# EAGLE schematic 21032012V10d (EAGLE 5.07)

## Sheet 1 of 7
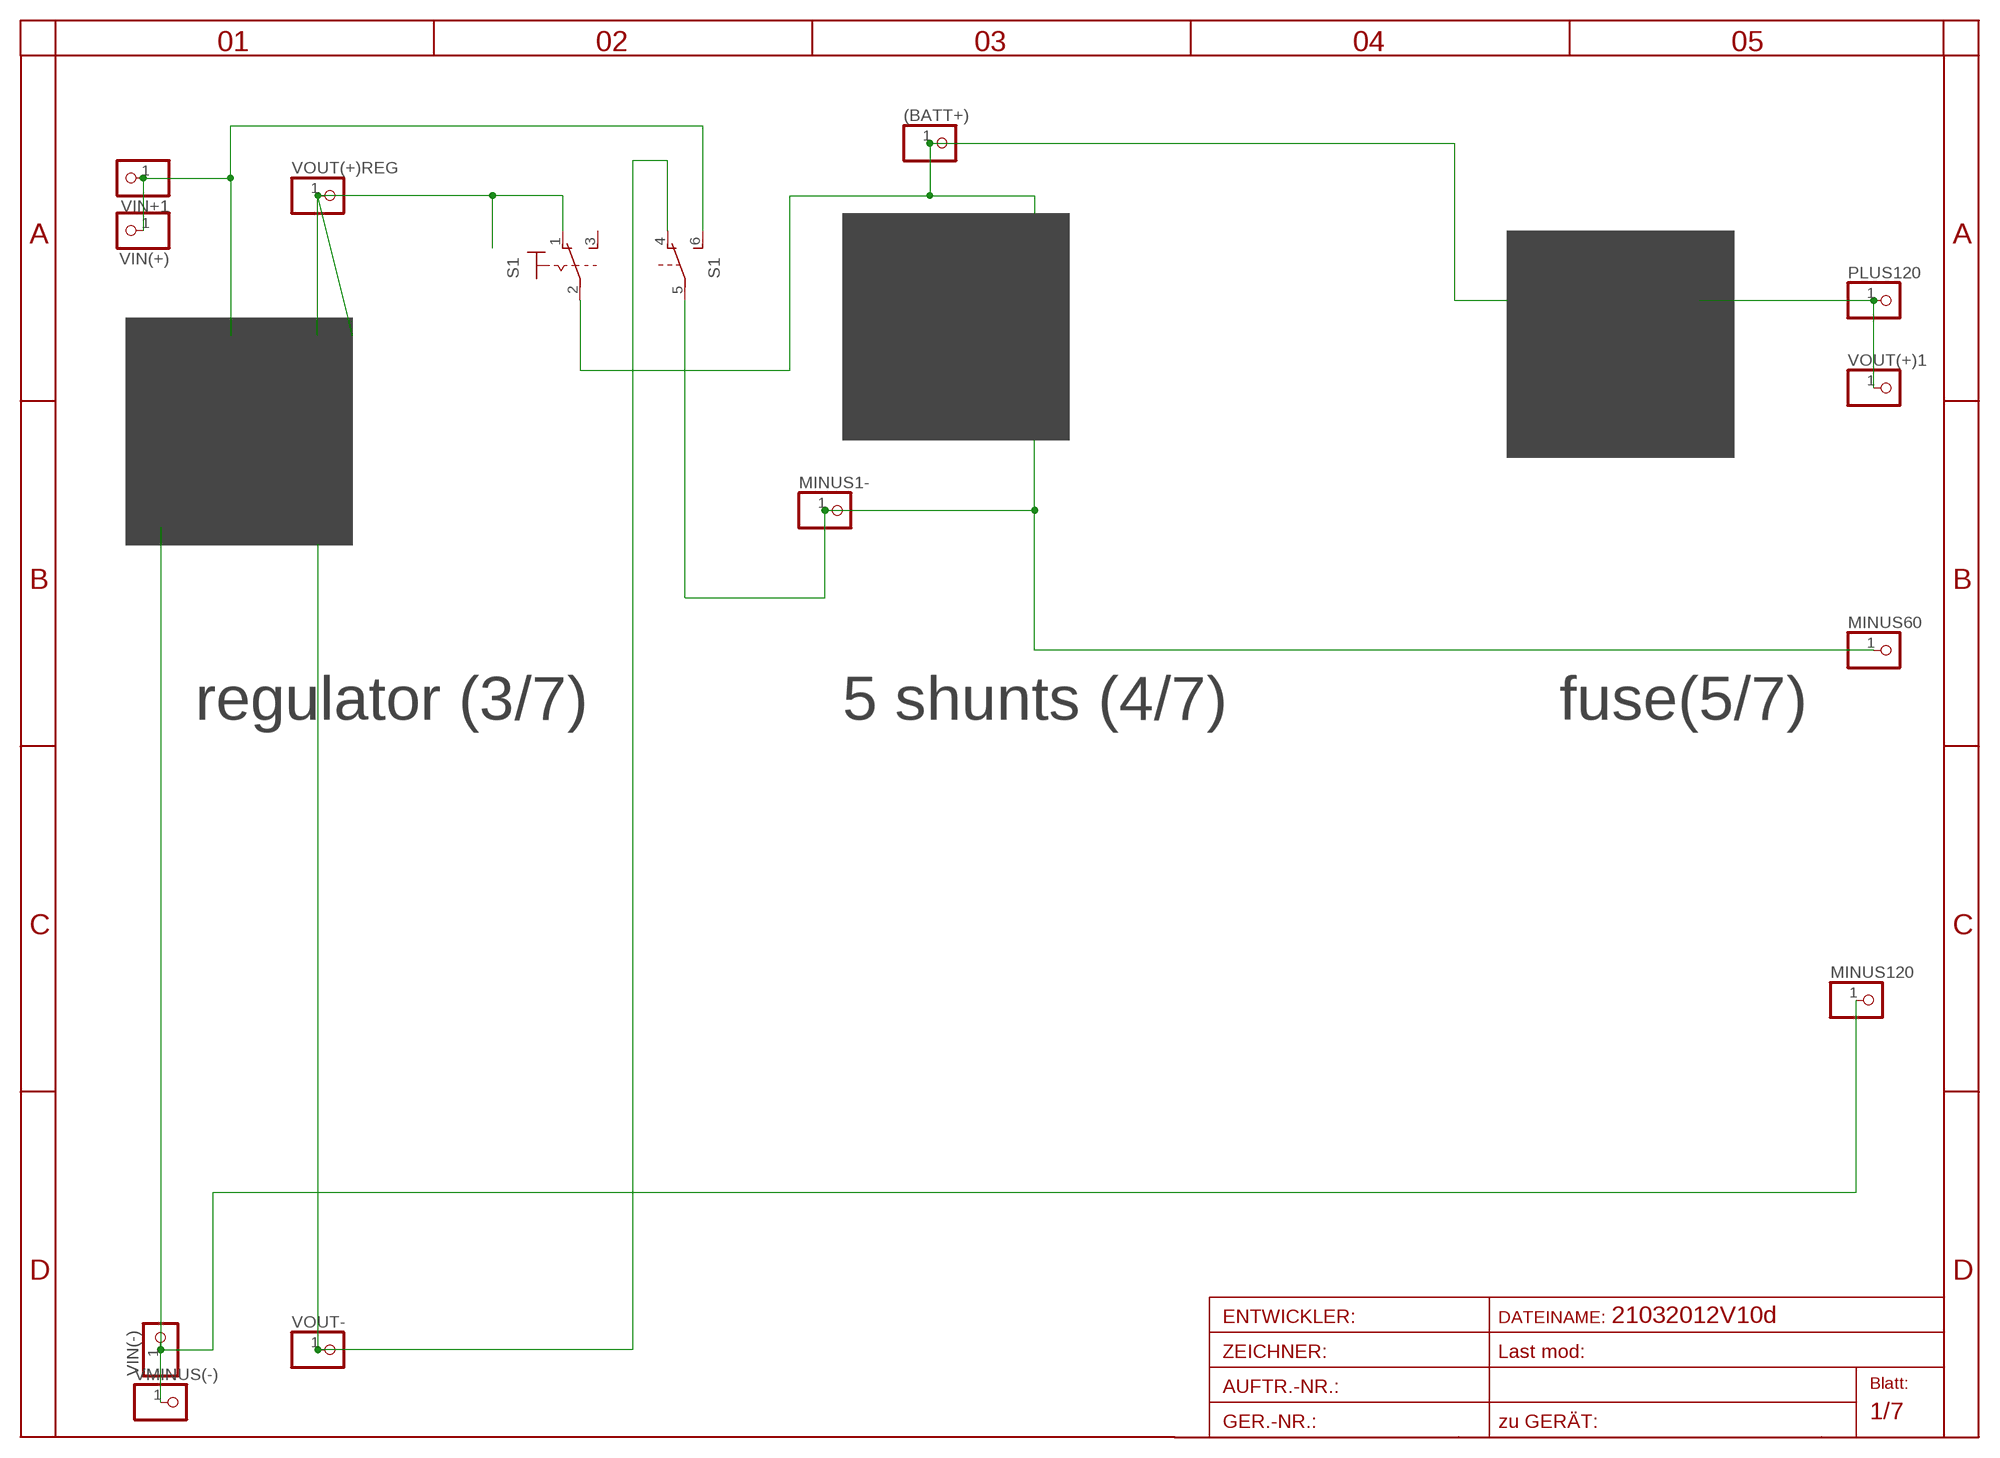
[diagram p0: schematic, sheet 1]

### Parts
(BATT+)  PINHD-1X14.5MM  [1X4MM5]
MINUS1-  PINHD-1X14.5MM  [1X4MM5]
MINUS60  PINHD-1X14.5MM  [1X4MM5]
MINUS120  PINHD-1X14.5MM  [1X4MM5]
PLUS120  PINHD-1X14.5MM  [1X4MM5]
S1  320-938320NEW  [320NEW]
VIN(+)  PINHD-1X11MM6  [1X1MM8]
VIN(-)  PINHD-1X1  [1X01]
VIN+1  PINHD-1X1  [1X01]
VMINUS(-)  PINHD-1X11MM6  [1X1MM8]
VOUT(+)1  PINHD-1X11X0.4  [1X01]
VOUT(+)REG  PINHD-1X11X0.4  [1X01]
VOUT-  PINHD-1X11X0.4  [1X01]

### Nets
BATT-: MINUS1-.1 MINUS60.1 S1.5(B:P) ; also sheet 4,5,6,7
IN-: MINUS120.1 VIN(-).1 VMINUS(-).1 ; also sheet 3
PLUS11: (BATT+).1 S1.2(1:P) ; also sheet 4,5,6,7
V+OUT: PLUS120.1 VOUT(+)1.1 ; also sheet 5
V-: S1.4(B:O) VOUT-.1 ; also sheet 3
VIN+: S1.6(B:S) VIN(+).1 VIN+1.1 ; also sheet 3
VOUT+REG: S1.1(1:O) VOUT(+)REG.1 ; also sheet 3
Unconnected: S1.3(1:S)

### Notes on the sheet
- regulator (3/7) | 5 shunts (4/7) | fuse(5/7)

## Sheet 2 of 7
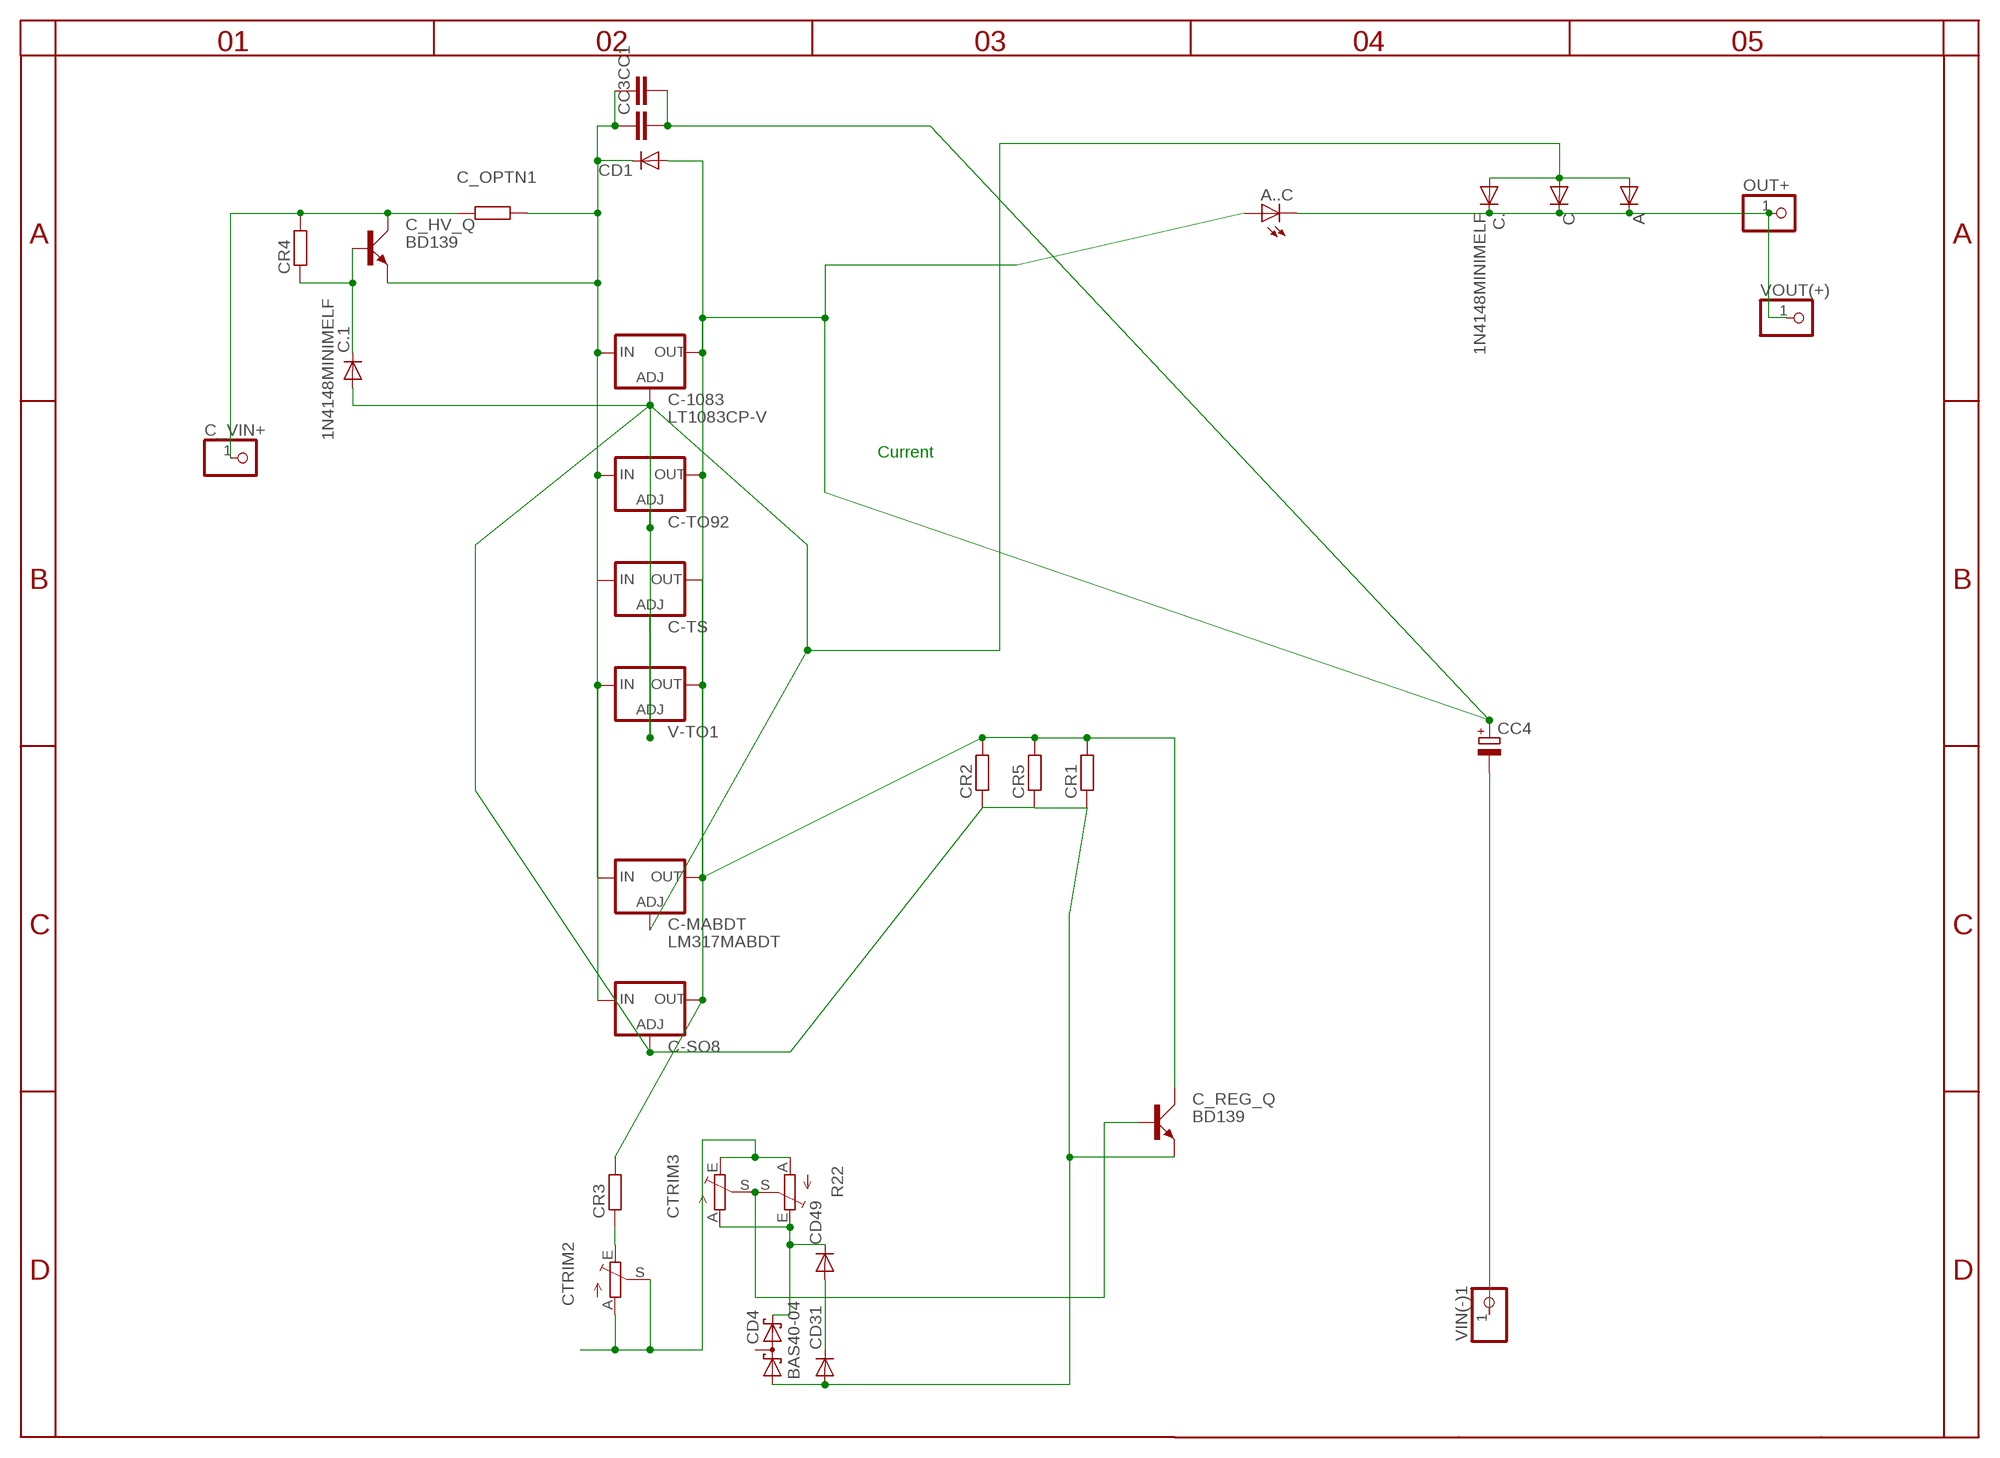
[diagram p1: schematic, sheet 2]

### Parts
A  DIODE-TO220V  [TO220ACS]
A..C  LED3MM  [LED3MM]
C  DIODE-SMB  [SMB]
C-1083  LT1083CP-V  [TO247S]
C-MABDT  LM317MABDT  [DPACK]
C-SO8  LM317LM-OUTPIN7  [SO08]
C-TO92  LM317LZS  [TO92S]
C-TS  LM317TS  [317TS]
C.  1N4148MINIMELF  [MINIMELF]
C.1  1N4148MINIMELF  [MINIMELF]
C_HV_Q  BD139  [TO126AV]
C_OPTN1  R-EU_R0805  [R0805]
C_REG_Q  BD139  [TO126AV]
C_VIN+  PINHD-1X11MM6  [1X1MM8]
CC1  C-EUC1206  [C1206]
CC3  C-EU050-025X075  [C050-025X075]
CC4  CPOL-EUE5-6  [E5-6]
CD1  DIODE-MINIMELF  [MINIMELF]
CD4  BAS40-04  [SOT23]
CD31  DIODE-MINIMELF  [MINIMELF]
CD49  DIODE-MINIMELF  [MINIMELF]
CR1  R-EU_R5025  [R5025]
CR2  R-EU_R1206  [R1206]
CR3  R-EU_R1206  [R1206]
CR4  R-EU_R1206  [R1206]
CR5  R-EU_R1210  [R1210]
CTRIM2  TRIM_EU-EVND_H  [EVND8AA]
CTRIM3  TRIM_EU-EVND_H  [EVND8AA]
OUT+  PINHD-1X1  [1X01]
R22  TRIM_EU-RAND160  [RANDL]
V-TO1  LM317-TO3  [TO3-K02]
VIN(-)1  PINHD-1X1  [1X01]
VOUT(+)  PINHD-1X11X0.4  [1X01]

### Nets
ADJUST: A.A C-1083.1(ADJ) C-MABDT.1(ADJ) C-SO8.4(ADJ) C-TO92.1(ADJ) C-TS.1(ADJ) C.1.A C..A C.A C_REG_Q.E CD4.1(A1) CD31.A CR1.1 CR2.1 CR5.1 V-TO1.2(ADJ)
B1: C_REG_Q.B CTRIM3.S R22.S
INPUT+: C-1083.3(IN) C-MABDT.3(IN) C-SO8.1(IN) C-TO92.3(IN) C-TS.3(IN) C_HV_Q.E C_OPTN1.1 CC1.1 CC3.1 CD1.C V-TO1.1(IN)
MINUS: CD4.2(C2) CD49.C CTRIM3.A R22.E
N$5: CTRIM2.A CTRIM2.S CTRIM3.E R22.A
N$6: CR3.1 CTRIM2.E
N$9: CC4.- VIN(-)1.1
N$54: CD31.C CD49.A
N$84: C.1.C C_HV_Q.B CR4.1
N$85: C_HV_Q.C C_OPTN1.2 C_VIN+.1 CR4.2
OUT1: A..C.A C-1083.2(OUT) C-MABDT.4(OUT) C-SO8.7(OUT) C-TO92.2(OUT) C-TS.2(OUT) C_REG_Q.C CC1.2 CC3.2 CC4.+ CD1.A CR1.2 CR2.2 CR3.2 CR5.2 V-TO1.3(OUT)
OUT+: A..C.K(C) A.C C..C C.C OUT+.1 VOUT(+).1
Unconnected: CD4.3(C1A2)

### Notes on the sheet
- Current

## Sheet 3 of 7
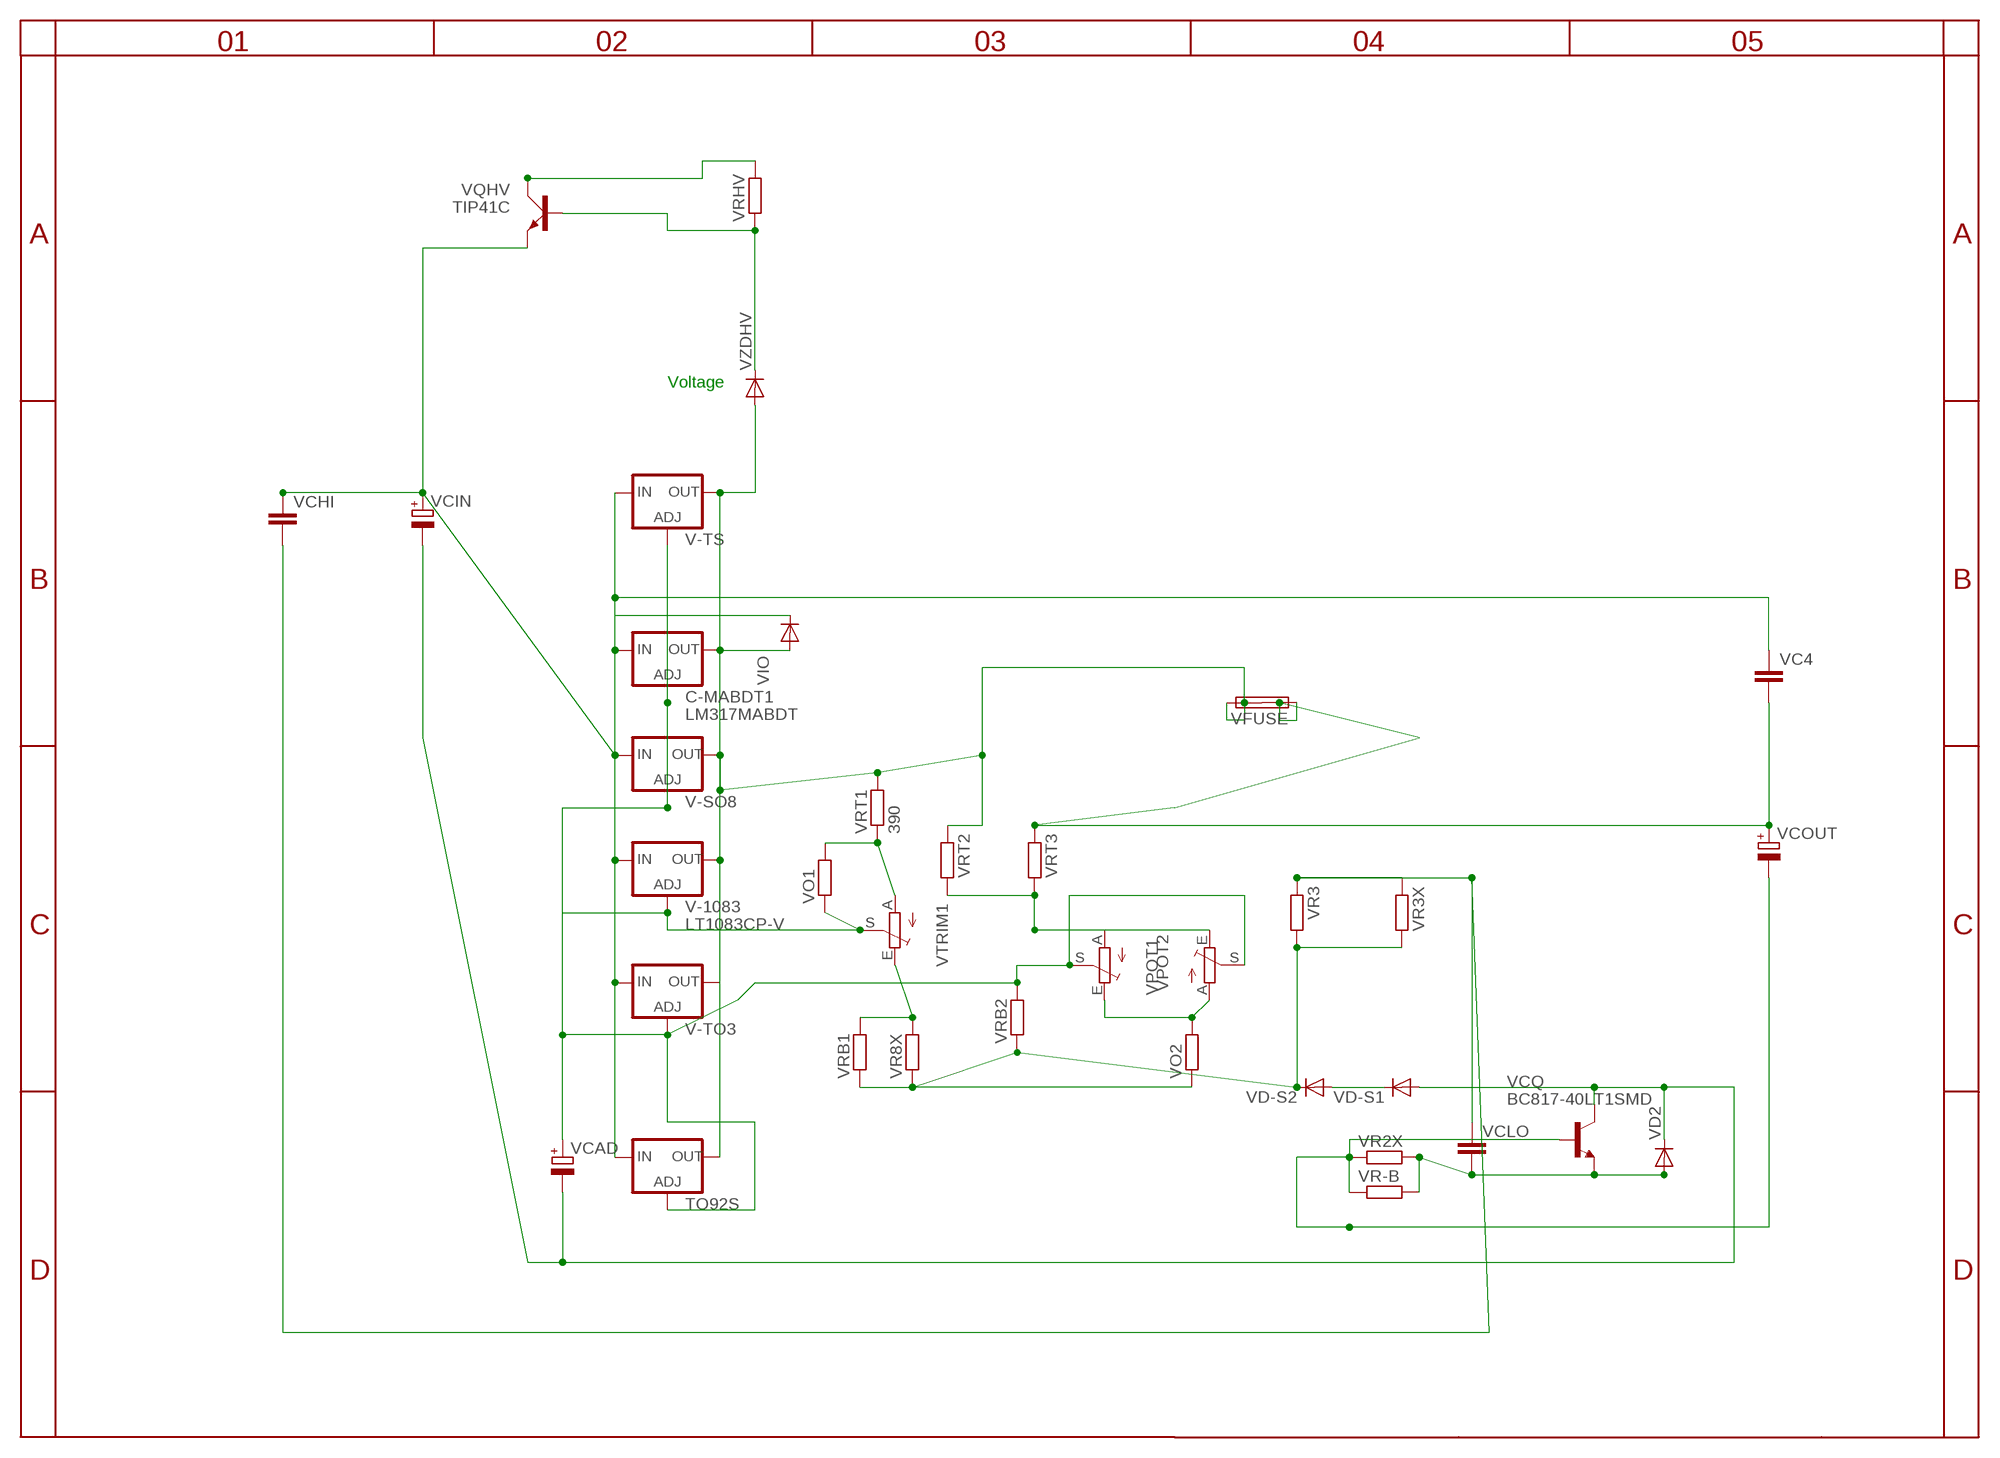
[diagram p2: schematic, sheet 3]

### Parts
C-MABDT1  LM317MABDT  [DPACK]
TO92S  LM317LZS  [TO92S]
V-1083  LT1083CP-V  [TO247S]
V-SO8  LM317LM-OUTPIN7  [SO08]
V-TO3  LM317-TO3  [TO3-K02]
V-TS  LM317TS  [317TS]
VC4  C-EUC1206  [C1206]
VCAD  CPOL-EUE2.5-6  [E2,5-6]
VCHI  C-EU050-025X075  [C050-025X075]
VCIN  CPOL-EUE2.5-6  [E2,5-6]
VCLO  C-EU050-025X075  [C050-025X075]
VCOUT  CPOL-EUE5-8.5  [E5-8,5]
VCQ  BC817-40LT1SMD  [SOT23-BEC]
VD2  DIODE-MINIMELF  [MINIMELF]
VD-S1  DIODE-MINIMELF  [MINIMELF]
VD-S2  DIODE-MINIMELF  [MINIMELF]
VFUSE  SHK20Q  [SHK20Q]
VIO  DIODE-MINIMELF  [MINIMELF]
VO1  R-EU_0204/2V  [0204V]
VO2  R-EU_0204/2V  [0204V]
VPOT1  TRIM_EU-RAND160  [RANDL]
VPOT2  TRIM_EU-S64W  [S64W]
VQHV  TIP41C  [TO220AV]
VR2X  R-EU_0617/17  [0617/17]
VR3  R-EU_0204/5  [0204/5]
VR3X  R-EU_R1206  [R1206]
VR8X  R-EU_0204/2V  [0204V]
VR-B  R-EU_R2010  [R2010]
VRB1  R-EU_R1206  [R1206]
VRB2  R-EU_R1206  [R1206]
VRHV  R-EU_R1206  [R1206]
VRT1  390  R-EU_0207/15  [0207/15]
VRT2  R-EU_R1206  [R1206]
VRT3  R-EU_R1206  [R1206]
VTRIM1  TRIM_EU-EVND_H  [EVND8AA]
VZDHV  DIODE-MINIMELF  [MINIMELF]

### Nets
ADJ2: C-MABDT1.1(ADJ) TO92S.1(ADJ) V-1083.1(ADJ) V-SO8.4(ADJ) V-TO3.2(ADJ) V-TS.1(ADJ) VCAD.+ VO1.1 VPOT1.S VPOT2.S VRB2.2 VTRIM1.S
IN+1: C-MABDT1.3(IN) TO92S.3(IN) V-1083.3(IN) V-SO8.1(IN) V-TO3.1(IN) V-TS.3(IN) VC4.1 VCHI.1 VCIN.+ VIO.C VQHV.E
IN-: VCLO.2 VCQ.E VD2.A VR2X.2 VR-B.2 ; also sheet 1
N$1: VO2.2 VPOT1.E VPOT2.A
N$2: VPOT1.A VPOT2.E VRT2.2 VRT3.2
N$3: VR8X.2 VRB1.2 VTRIM1.E
N$4: VO1.2 VRT1.1 VTRIM1.A
N$7: VCHI.2 VCLO.1 VR3.1 VR3X.1
N$10: VQHV.B VRHV.1 VZDHV.C
N$12: VD-S2.C VO2.1 VR3.2 VR3X.2 VR8X.1 VRB1.1 VRB2.1
N$13: VD-S1.C VD-S2.A
OUT2: C-MABDT1.4(OUT) TO92S.2(OUT) V-1083.2(OUT) V-SO8.7(OUT) V-TO3.3(OUT) V-TS.2(OUT) VFUSE.2A VFUSE.2B VIO.A VRT1.2 VRT2.1 VZDHV.A
V-: VCOUT.- VCQ.B VR2X.1 VR-B.1 ; also sheet 1
VIN+: VQHV.C VRHV.2 ; also sheet 1
VIRT-: VCAD.- VCIN.- VCQ.C VD2.C VD-S1.A
VOUT+REG: VC4.2 VCOUT.+ VFUSE.1A VFUSE.1B VRT3.1 ; also sheet 1

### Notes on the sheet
- Voltage

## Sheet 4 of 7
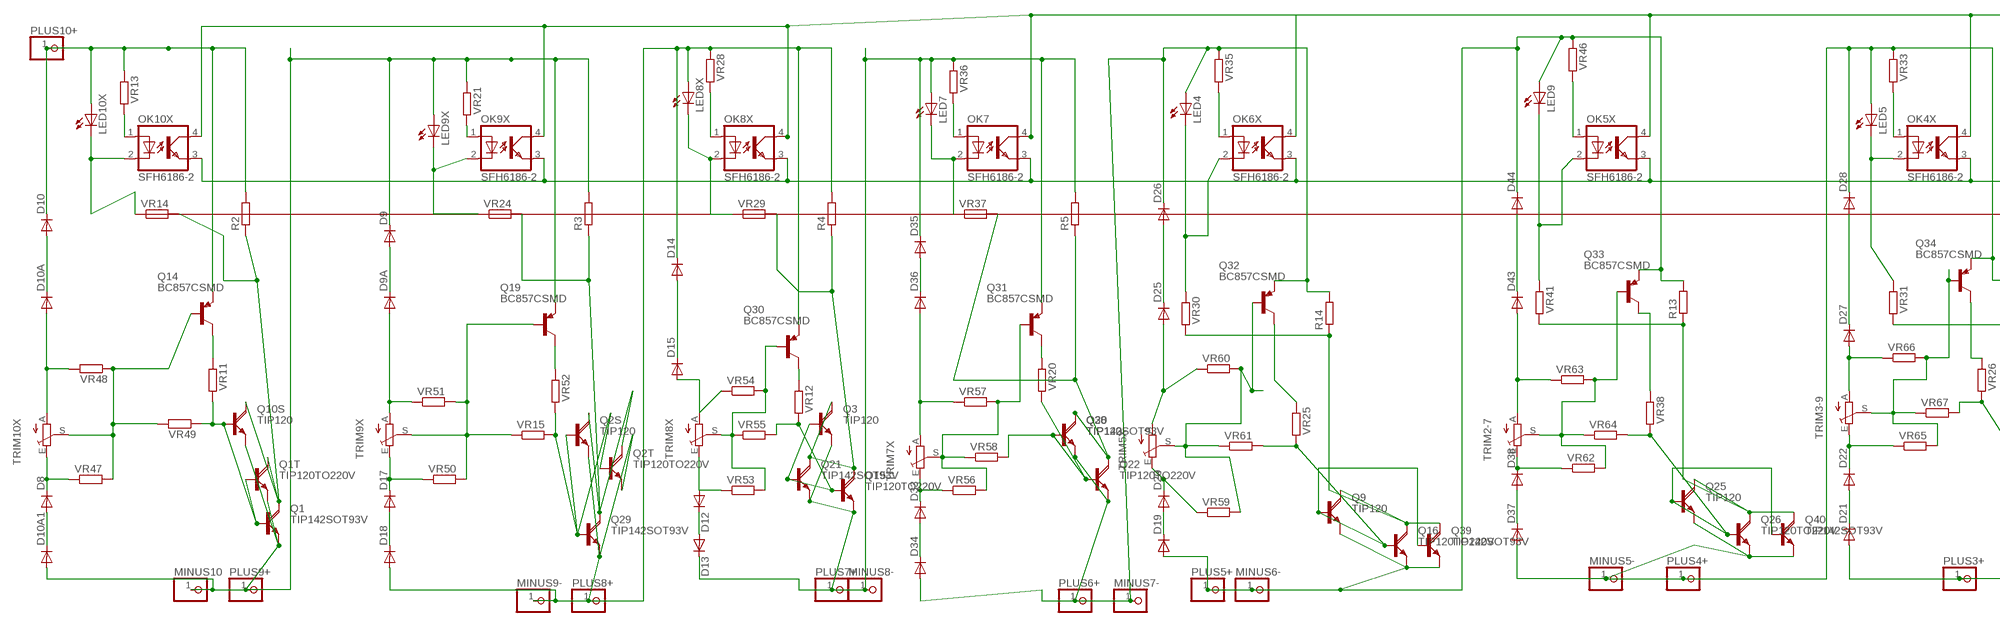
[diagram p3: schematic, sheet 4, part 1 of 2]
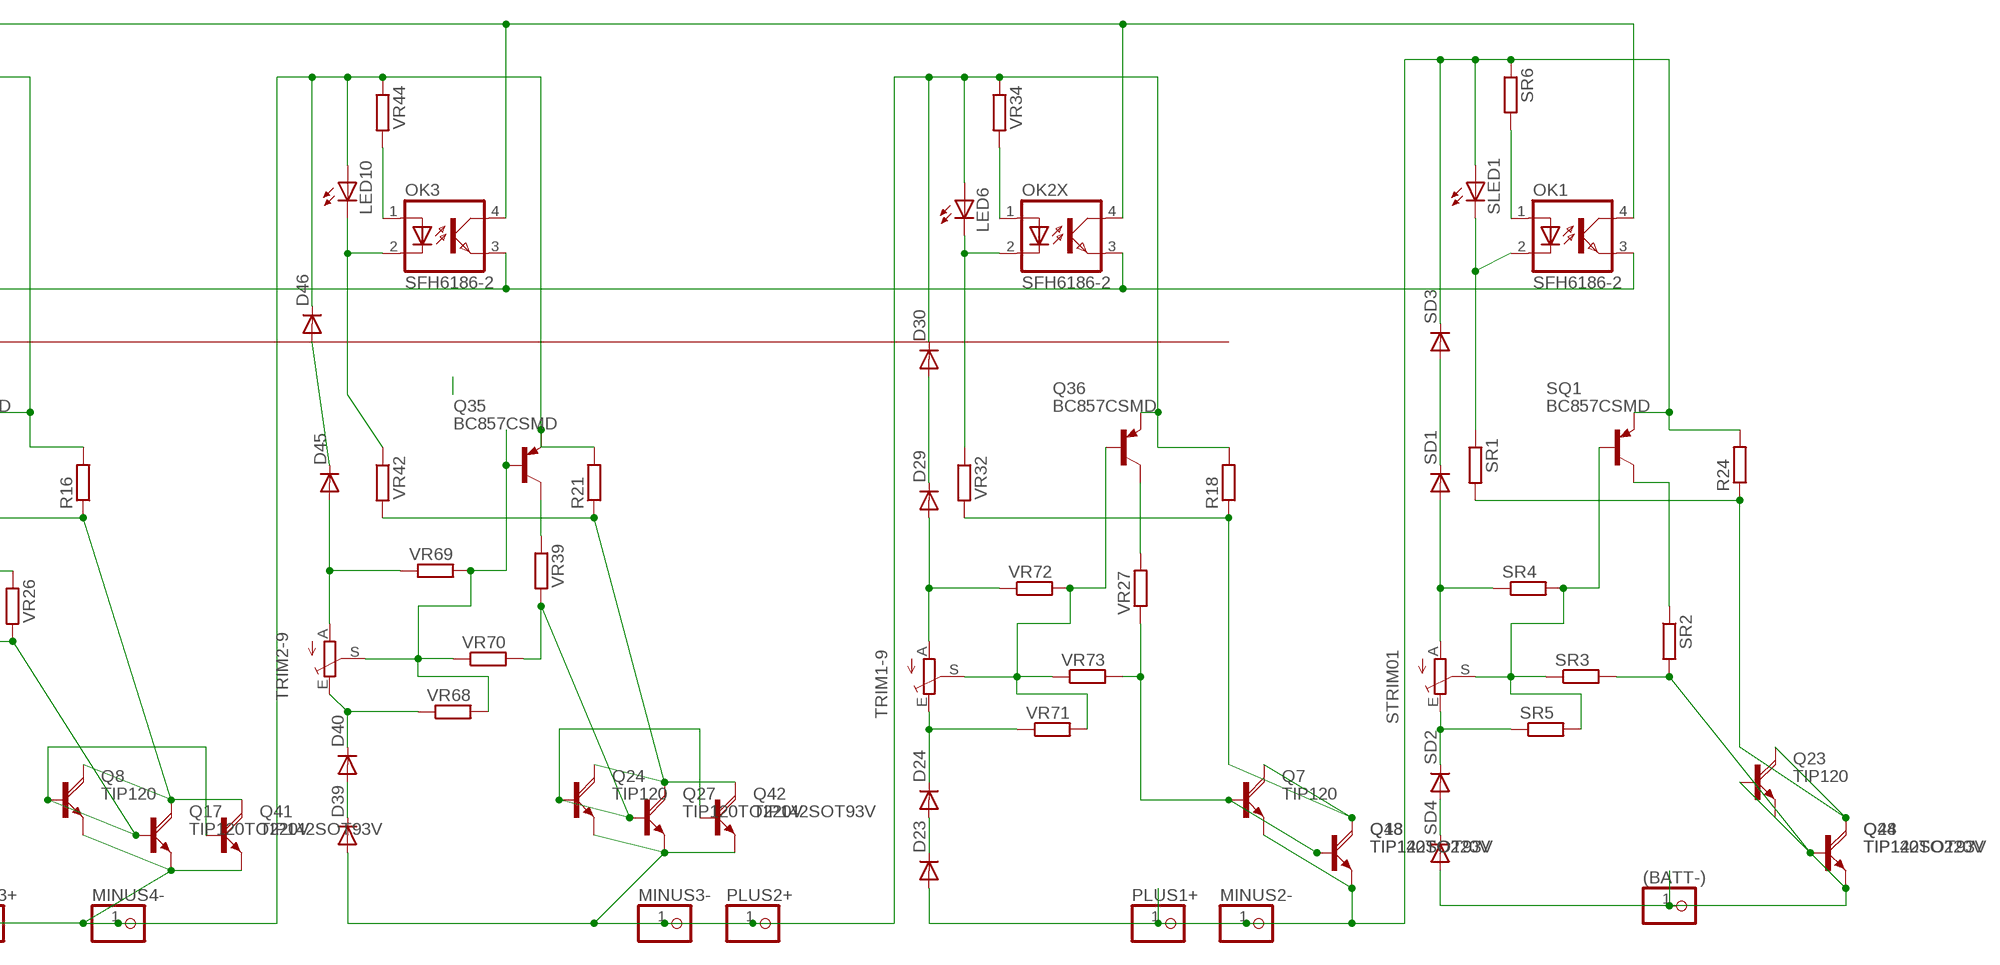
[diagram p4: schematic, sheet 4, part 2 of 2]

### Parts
(BATT-)  PINHD-1X11X0.4  [1X01]
D8  DIODE-MINIMELF  [MINIMELF]
D9  DIODE-MINIMELF  [MINIMELF]
D9A  DIODE-MINIMELF  [MINIMELF]
D10  DIODE-MINIMELF  [MINIMELF]
D10A  DIODE-MINIMELF  [MINIMELF]
D10A1  DIODE-MINIMELF  [MINIMELF]
D12  DIODE-MINIMELF  [MINIMELF]
D13  DIODE-MINIMELF  [MINIMELF]
D14  DIODE-MINIMELF  [MINIMELF]
D15  DIODE-MINIMELF  [MINIMELF]
D17  DIODE-MINIMELF  [MINIMELF]
D18  DIODE-MINIMELF  [MINIMELF]
D19  DIODE-MINIMELF  [MINIMELF]
D20  DIODE-MINIMELF  [MINIMELF]
D21  DIODE-MINIMELF  [MINIMELF]
D22  DIODE-MINIMELF  [MINIMELF]
D23  DIODE-MINIMELF  [MINIMELF]
D24  DIODE-MINIMELF  [MINIMELF]
D25  DIODE-MINIMELF  [MINIMELF]
D26  DIODE-MINIMELF  [MINIMELF]
D27  DIODE-MINIMELF  [MINIMELF]
D28  DIODE-MINIMELF  [MINIMELF]
D29  DIODE-MINIMELF  [MINIMELF]
D30  DIODE-MINIMELF  [MINIMELF]
D33  DIODE-MINIMELF  [MINIMELF]
D34  DIODE-MINIMELF  [MINIMELF]
D35  DIODE-MINIMELF  [MINIMELF]
D36  DIODE-MINIMELF  [MINIMELF]
D37  DIODE-MINIMELF  [MINIMELF]
D38  DIODE-MINIMELF  [MINIMELF]
D39  DIODE-MINIMELF  [MINIMELF]
D40  DIODE-MINIMELF  [MINIMELF]
D43  DIODE-MINIMELF  [MINIMELF]
D44  DIODE-MINIMELF  [MINIMELF]
D45  DIODE-MINIMELF  [MINIMELF]
D46  DIODE-MINIMELF  [MINIMELF]
LED4  LEDCHIPLED_1206  [CHIPLED_1206]
LED5  LEDCHIPLED_1206  [CHIPLED_1206]
LED6  LEDCHIPLED_1206  [CHIPLED_1206]
LED7  LEDCHIPLED_1206  [CHIPLED_1206]
LED8X  LEDCHIPLED_1206  [CHIPLED_1206]
LED9  LEDCHIPLED_1206  [CHIPLED_1206]
LED9X  LEDCHIPLED_1206  [CHIPLED_1206]
LED10  LEDCHIPLED_1206  [CHIPLED_1206]
LED10X  LEDCHIPLED_1206  [CHIPLED_1206]
MINUS2-  PINHD-1X14.5MM  [1X4MM5]
MINUS3-  PINHD-1X14.5MM  [1X4MM5]
MINUS4-  PINHD-1X14.5MM  [1X4MM5]
MINUS5-  PINHD-1X14.5MM  [1X4MM5]
MINUS6-  PINHD-1X14.5MM  [1X4MM5]
MINUS7-  PINHD-1X14.5MM  [1X4MM5]
MINUS8-  PINHD-1X14.5MM  [1X4MM5]
MINUS9-  PINHD-1X14.5MM  [1X4MM5]
MINUS10  PINHD-1X14.5MM  [1X4MM5]
OK1  SFH6186-2  [SMD4]
OK2X  SFH6186-2  [SMD4]
OK3  SFH6186-2  [SMD4]
OK4X  SFH6186-2  [SMD4]
OK5X  SFH6186-2  [SMD4]
OK6X  SFH6186-2  [SMD4]
OK7  SFH6186-2  [SMD4]
OK8X  SFH6186-2  [SMD4]
OK9X  SFH6186-2  [SMD4]
OK10X  SFH6186-2  [SMD4]
PLUS1+  PINHD-1X11X0.4  [1X01]
PLUS2+  PINHD-1X11X0.4  [1X01]
PLUS3+  PINHD-1X11X0.4  [1X01]
PLUS4+  PINHD-1X11X0.4  [1X01]
PLUS5+  PINHD-1X11X0.4  [1X01]
PLUS6+  PINHD-1X11X0.4  [1X01]
PLUS7+  PINHD-1X11X0.4  [1X01]
PLUS8+  PINHD-1X11X0.4  [1X01]
PLUS9+  PINHD-1X11X0.4  [1X01]
PLUS10+  PINHD-1X11X0.4  [1X01]
Q1  TIP142SOT93V  [SOT93V]
Q1T  TIP120TO220V  [TO220AV]
Q2S  TIP120  TIP120DPAK  [D-PAK_TO252AA]
Q2T  TIP120TO220V  [TO220AV]
Q3  TIP120  TIP120DPAK  [D-PAK_TO252AA]
Q7  TIP120  TIP120DPAK  [D-PAK_TO252AA]
Q8  TIP120  TIP120DPAK  [D-PAK_TO252AA]
Q9  TIP120  TIP120DPAK  [D-PAK_TO252AA]
Q10S  TIP120  TIP120DPAK  [D-PAK_TO252AA]
Q14  BC857CSMD  [SOT23-BEC]
Q15  TIP120TO220V  [TO220AV]
Q16  TIP120TO220V  [TO220AV]
Q17  TIP120TO220V  [TO220AV]
Q18  TIP120TO220V  [TO220AV]
Q19  BC857CSMD  [SOT23-BEC]
Q20  TIP120  TIP120DPAK  [D-PAK_TO252AA]
Q21  TIP142SOT93V  [SOT93V]
Q22  TIP120TO220V  [TO220AV]
Q23  TIP120  TIP120DPAK  [D-PAK_TO252AA]
Q24  TIP120  TIP120DPAK  [D-PAK_TO252AA]
Q25  TIP120  TIP120DPAK  [D-PAK_TO252AA]
Q26  TIP120TO220V  [TO220AV]
Q27  TIP120TO220V  [TO220AV]
Q28  TIP120TO220V  [TO220AV]
Q29  TIP142SOT93V  [SOT93V]
Q30  BC857CSMD  [SOT23-BEC]
Q31  BC857CSMD  [SOT23-BEC]
Q32  BC857CSMD  [SOT23-BEC]
Q33  BC857CSMD  [SOT23-BEC]
Q34  BC857CSMD  [SOT23-BEC]
Q35  BC857CSMD  [SOT23-BEC]
Q36  BC857CSMD  [SOT23-BEC]
Q38  TIP142SOT93V  [SOT93V]
Q39  TIP142SOT93V  [SOT93V]
Q40  TIP142SOT93V  [SOT93V]
Q41  TIP142SOT93V  [SOT93V]
Q42  TIP142SOT93V  [SOT93V]
Q43  TIP142SOT93V  [SOT93V]
Q44  TIP142SOT93V  [SOT93V]
R2  R-EU_CERAM55  [CERAM55]
R3  R-EU_CERAM55  [CERAM55]
R4  R-EU_CERAM55  [CERAM55]
R5  R-EU_CERAM55  [CERAM55]
R13  R-EU_CERAM55  [CERAM55]
R14  R-EU_CERAM55  [CERAM55]
R16  R-EU_CERAM55  [CERAM55]
R18  R-EU_CERAM55  [CERAM55]
R21  R-EU_CERAM55  [CERAM55]
R24  R-EU_CERAM55  [CERAM55]
SD1  DIODE-MINIMELF  [MINIMELF]
SD2  DIODE-MINIMELF  [MINIMELF]
SD3  DIODE-MINIMELF  [MINIMELF]
SD4  DIODE-MINIMELF  [MINIMELF]
SLED1  LEDCHIPLED_1206  [CHIPLED_1206]
SQ1  BC857CSMD  [SOT23-BEC]
SR1  R-EU_R1206  [R1206]
SR2  R-EU_R1206  [R1206]
SR3  R-EU_R0805  [R0805]
SR4  R-EU_R0805  [R0805]
SR5  R-EU_R0805  [R0805]
SR6  R-EU_R1206  [R1206]
STRIM01  TRIM_EU-S64W  [S64W]
TRIM1-9  TRIM_EU-S64W  [S64W]
TRIM2-7  TRIM_EU-S64W  [S64W]
TRIM2-9  TRIM_EU-S64W  [S64W]
TRIM3-9  TRIM_EU-S64W  [S64W]
TRIM5X  TRIM_EU-S64W  [S64W]
TRIM7X  TRIM_EU-S64W  [S64W]
TRIM8X  TRIM_EU-S64W  [S64W]
TRIM9X  TRIM_EU-S64W  [S64W]
TRIM10X  TRIM_EU-S64W  [S64W]
VR11  R-EU_R1206  [R1206]
VR12  R-EU_R1206  [R1206]
VR13  R-EU_R1206  [R1206]
VR14  R-EU_R1206  [R1206]
VR15  R-EU_R0805  [R0805]
VR20  R-EU_R1206  [R1206]
VR21  R-EU_R1206  [R1206]
VR24  R-EU_R1206  [R1206]
VR25  R-EU_R1206  [R1206]
VR26  R-EU_R1206  [R1206]
VR27  R-EU_R1206  [R1206]
VR28  R-EU_R1206  [R1206]
VR29  R-EU_R1206  [R1206]
VR30  R-EU_R1206  [R1206]
VR31  R-EU_R1206  [R1206]
VR32  R-EU_R1206  [R1206]
VR33  R-EU_R1206  [R1206]
VR34  R-EU_R1206  [R1206]
VR35  R-EU_R1206  [R1206]
VR36  R-EU_R1206  [R1206]
VR37  R-EU_R1206  [R1206]
VR38  R-EU_R1206  [R1206]
VR39  R-EU_R1206  [R1206]
VR41  R-EU_R1206  [R1206]
VR42  R-EU_R1206  [R1206]
VR44  R-EU_R1206  [R1206]
VR46  R-EU_R1206  [R1206]
VR47  R-EU_R0805  [R0805]
VR48  R-EU_R0805  [R0805]
VR49  R-EU_R0805  [R0805]
VR50  R-EU_R0805  [R0805]
VR51  R-EU_R0805  [R0805]
VR52  R-EU_R1206  [R1206]
VR53  R-EU_R0805  [R0805]
VR54  R-EU_R0805  [R0805]
VR55  R-EU_R0805  [R0805]
VR56  R-EU_R0805  [R0805]
VR57  R-EU_R0805  [R0805]
VR58  R-EU_R0805  [R0805]
VR59  R-EU_R0805  [R0805]
VR60  R-EU_R0805  [R0805]
VR61  R-EU_R0805  [R0805]
VR62  R-EU_R0805  [R0805]
VR63  R-EU_R0805  [R0805]
VR64  R-EU_R0805  [R0805]
VR65  R-EU_R0805  [R0805]
VR66  R-EU_R0805  [R0805]
VR67  R-EU_R0805  [R0805]
VR68  R-EU_R0805  [R0805]
VR69  R-EU_R0805  [R0805]
VR70  R-EU_R0805  [R0805]
VR71  R-EU_R0805  [R0805]
VR72  R-EU_R0805  [R0805]
VR73  R-EU_R0805  [R0805]

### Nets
B: Q14.B TRIM10X.S VR47.2 VR48.1 VR49.2
BATT-: (BATT-).1 Q23.3(E) Q28.E Q44.E SD4.A ; also sheet 1,5,6,7
E2: D23.A MINUS2-.1 PLUS1+.1 Q7.3(E) Q18.E Q43.E R24.2 SD3.C SLED1.A SQ1.E SR6.1
E3: D30.C D39.A LED6.A MINUS3-.1 PLUS2+.1 Q24.3(E) Q27.E Q36.E Q42.E R18.2 VR34.1
E4: D21.A D46.C LED10.A MINUS4-.1 PLUS3+.1 Q8.3(E) Q17.E Q35.E Q41.E R21.2 VR44.1
E5: D28.C D37.A LED5.A MINUS5-.1 PLUS4+.1 Q25.3(E) Q26.E Q34.E Q40.E R16.2 VR33.1
E6: D19.A D44.C LED9.A MINUS6-.1 PLUS5+.1 Q9.3(E) Q16.E Q33.E Q39.E R13.2 VR46.1
E7: D26.C D34.A LED4.A MINUS7-.1 PLUS6+.1 Q20.3(E) Q22.E Q32.E Q38.E R14.2 VR35.1
E8: D13.C D35.C LED7.A MINUS8-.1 PLUS7+.1 Q3.3(E) Q15.E Q21.E Q31.E R5.2 VR36.1
E9: D14.C D18.A LED8X.A MINUS9-.1 PLUS8+.1 Q2S.3(E) Q2T.E Q29.E Q30.E R4.2 VR28.1
N$11: LED10X.C OK10X.2(C) VR14.1
N$14: D10A.A TRIM10X.A VR48.2
N$15: Q14.C VR11.1
N$16: OK8X.1(A) VR28.2
N$17: D10.A D10A.C
N$20: D9A.A TRIM9X.A VR51.1
N$23: OK10X.1(A) VR13.2
N$24: D8.A D10A1.C
N$25: Q1.B Q1T.B Q10S.1(B) VR11.2 VR49.1
N$26: D15.A TRIM8X.A VR54.1
N$27: D12.A TRIM8X.E VR53.1
N$29: D14.A D15.C
N$31: LED8X.C OK8X.2(C) VR29.1
N$32: D12.C D13.A
N$33: Q3.1(B) Q15.B Q21.B VR12.2 VR55.2
N$45: Q35.C VR39.1
N$50: Q9.1(B) Q16.B Q39.B VR25.2 VR61.2
N$51: Q8.1(B) Q17.B Q41.B VR26.2 VR67.2
N$52: Q7.1(B) Q18.B Q43.B VR27.1 VR73.2
N$55: D33.A D34.C
N$56: D9.A D9A.C
N$57: D33.C TRIM7X.E VR56.1
N$62: D27.A TRIM3-9.A VR66.1
N$63: D22.C TRIM3-9.E VR65.1
N$64: Q34.B TRIM3-9.S VR65.2 VR66.2 VR67.1
N$65: Q31.B TRIM7X.S VR56.2 VR57.2 VR58.1
N$66: D25.A TRIM5X.A VR60.1
N$67: Q31.C VR20.1
N$68: D19.C D20.A
N$70: D21.C D22.A
N$71: D25.C D26.A
N$72: D20.C TRIM5X.E VR59.1
N$73: D27.C D28.A
N$74: D29.C D30.A
N$77: LED4.C OK6X.2(C) VR30.1
N$78: LED5.C OK4X.2(C) VR31.1
N$79: LED6.C OK2X.2(C) VR32.1
N$80: OK6X.1(A) VR35.2
N$81: OK4X.1(A) VR33.2
N$82: OK2X.1(A) VR34.2
N$86: Q19.B TRIM9X.S VR15.1 VR50.2 VR51.2
N$87: Q2S.1(B) Q2T.B Q29.B VR15.2 VR52.2
N$88: D36.A TRIM7X.A VR57.1
N$89: D37.C D38.A
N$91: D35.A D36.C
N$92: Q34.C VR26.1
N$93: Q20.1(B) Q22.B Q38.B VR20.2 VR58.2
N$94: LED9X.C OK9X.2(C) VR24.1
N$95: OK9X.1(A) VR21.2
N$99: OK7.1(A) VR36.2
N$100: LED7.C OK7.2(C) VR37.1
N$102: Q25.1(B) Q26.B Q40.B VR38.2 VR64.2
N$103: Q24.1(B) Q27.B Q42.B VR39.2 VR70.2
N$104: Q23.1(B) Q28.B Q44.B SR2.2 SR3.2
N$105: Q32.B TRIM5X.S VR59.2 VR60.2 VR61.1
N$106: D43.A TRIM2-7.A VR63.1
N$107: Q33.C VR38.1
N$108: D29.A TRIM1-9.A VR72.1
N$109: D40.C TRIM2-9.E VR68.1
N$110: D38.C TRIM2-7.E VR62.1
N$111: Q33.B TRIM2-7.S VR62.2 VR63.2 VR64.1
N$112: Q32.C VR25.1
N$113: Q35.B TRIM2-9.S VR68.2 VR69.2 VR70.1
N$115: D45.A TRIM2-9.A VR69.1
N$116: D24.C TRIM1-9.E VR71.1
N$118: D43.C D44.A
N$119: D45.C D46.A
N$120: SD1.C SD3.A
N$121: LED9.C OK5X.2(C) VR41.1
N$122: LED10.C OK3.2(C) VR42.1
N$123: OK1.2(C) SLED1.C SR1.1
N$124: OK5X.1(A) VR46.2
N$125: OK3.1(A) VR44.2
N$126: OK1.1(A) SR6.2
N$127: D17.C TRIM9X.E VR50.1
N$128: D8.C TRIM10X.E VR47.1
N$129: D17.A D18.C
N$130: Q30.C VR12.1
N$131: Q19.C VR52.1
N$132: Q30.B TRIM8X.S VR53.2 VR54.2 VR55.1
N$133: D39.C D40.A
N$134: Q36.B TRIM1-9.S VR71.2 VR72.2 VR73.1
N$137: D23.C D24.A
N$140: Q36.C VR27.2
N$141: SD1.A SR4.1 STRIM01.A
N$142: SD2.C SR5.1 STRIM01.E
N$143: SQ1.B SR3.1 SR4.2 SR5.2 STRIM01.S
N$144: SD2.A SD4.C
N$145: SQ1.C SR2.1
PLUS10: D9.C D10A1.A LED9X.A MINUS10.1 PLUS9+.1 Q1.E Q1T.E Q10S.3(E) Q19.E R3.2 VR21.1
PLUS11: D10.C LED10X.A PLUS10+.1 Q14.E R2.2 VR13.1 ; also sheet 1,5,6,7
Q0C: Q23.4(C) Q28.C Q44.C R24.1 SR1.2
Q1C: Q1.C Q1T.C Q10S.4(C) R2.1 VR14.2
Q2C: Q7.4(C) Q18.C Q43.C R18.1 VR32.2
Q3C: Q24.4(C) Q27.C Q42.C R21.1 VR42.2
Q4C: Q8.4(C) Q17.C Q41.C R16.1 VR31.2
Q5C: Q25.4(C) Q26.C Q40.C R13.1 VR41.2
Q6C: Q9.4(C) Q16.C Q39.C R14.1 VR30.2
Q7C: Q20.4(C) Q22.C Q38.C R5.1 VR37.2
Q8C: Q3.4(C) Q15.C Q21.C R4.1 VR29.2
Q9C: Q2S.4(C) Q2T.C Q29.C R3.1 VR24.2
VENTB: OK1.3(EMIT) OK2X.3(EMIT) OK3.3(EMIT) OK4X.3(EMIT) OK5X.3(EMIT) OK6X.3(EMIT) OK7.3(EMIT) OK8X.3(EMIT) OK9X.3(EMIT) OK10X.3(EMIT) ; also sheet 6
VENTMID: OK1.4(COL) OK2X.4(COL) OK3.4(COL) OK4X.4(COL) OK5X.4(COL) OK6X.4(COL) OK7.4(COL) OK8X.4(COL) OK9X.4(COL) OK10X.4(COL) ; also sheet 6

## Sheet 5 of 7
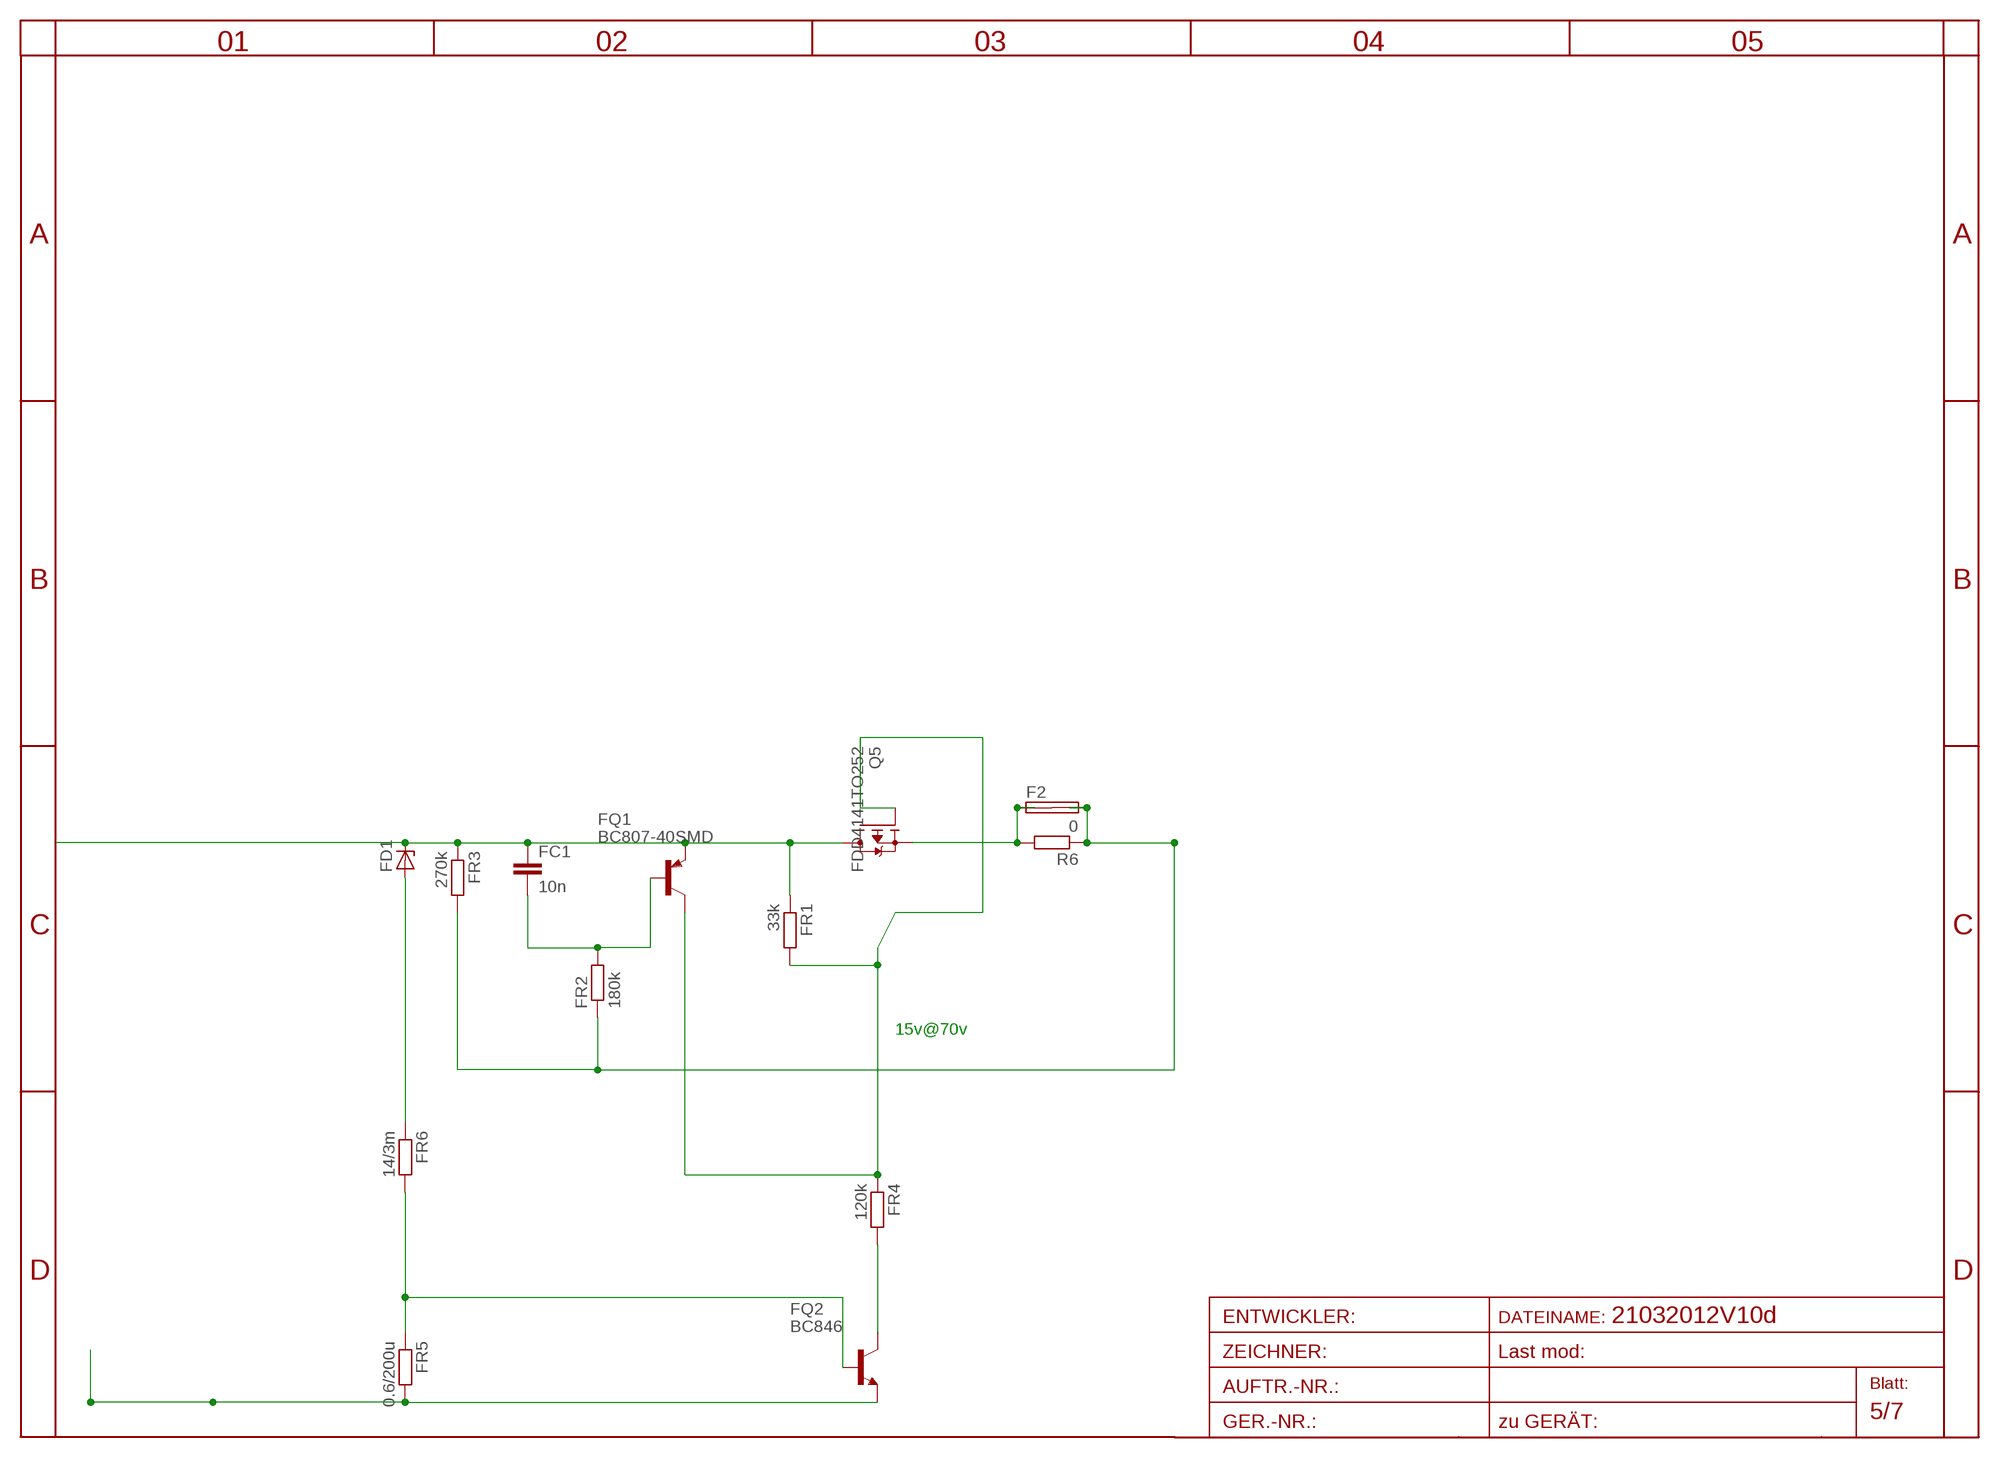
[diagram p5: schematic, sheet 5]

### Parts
F2  SHK20Q  [SHK20Q]
FC1  10n  C-EUC1206  [C1206]
FD1  ZENER-DIODESOD80C  [SOD80C]
FQ1  BC807-40SMD  [SOT23-BEC]
FQ2  BC846  [SOT23]
FR1  33k  R-EU_R1206  [R1206]
FR2  180k  R-EU_R1206  [R1206]
FR3  270k  R-EU_R1206  [R1206]
FR4  120k  R-EU_R1206  [R1206]
FR5  0.6/200u  R-EU_R1206  [R1206]
FR6  14/3m  R-EU_R1206  [R1206]
Q5  FDD4141TO252  [TO252]
R6  0  R-EU_0207/15  [0207/15]

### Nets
B-Q1: FC1.2 FQ1.B FR2.2
BATT-: FQ2.2(E) FR5.2 ; also sheet 1,4,6,7
D: F2.1A F2.1B Q5.3(S) R6.2
GATE: FQ1.C FR1.2 FR4.1 Q5.1(G)
N$18: FQ2.3(C) FR4.2
N$19: FD1.A FR6.1
N$21: FQ2.1(B) FR5.1 FR6.2
PLUS11: FC1.1 FD1.C FQ1.E FR1.1 FR3.1 Q5.2(D) ; also sheet 1,4,6,7
V+OUT: F2.2A F2.2B FR2.1 FR3.2 R6.1 ; also sheet 1

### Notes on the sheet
- 15v@70v

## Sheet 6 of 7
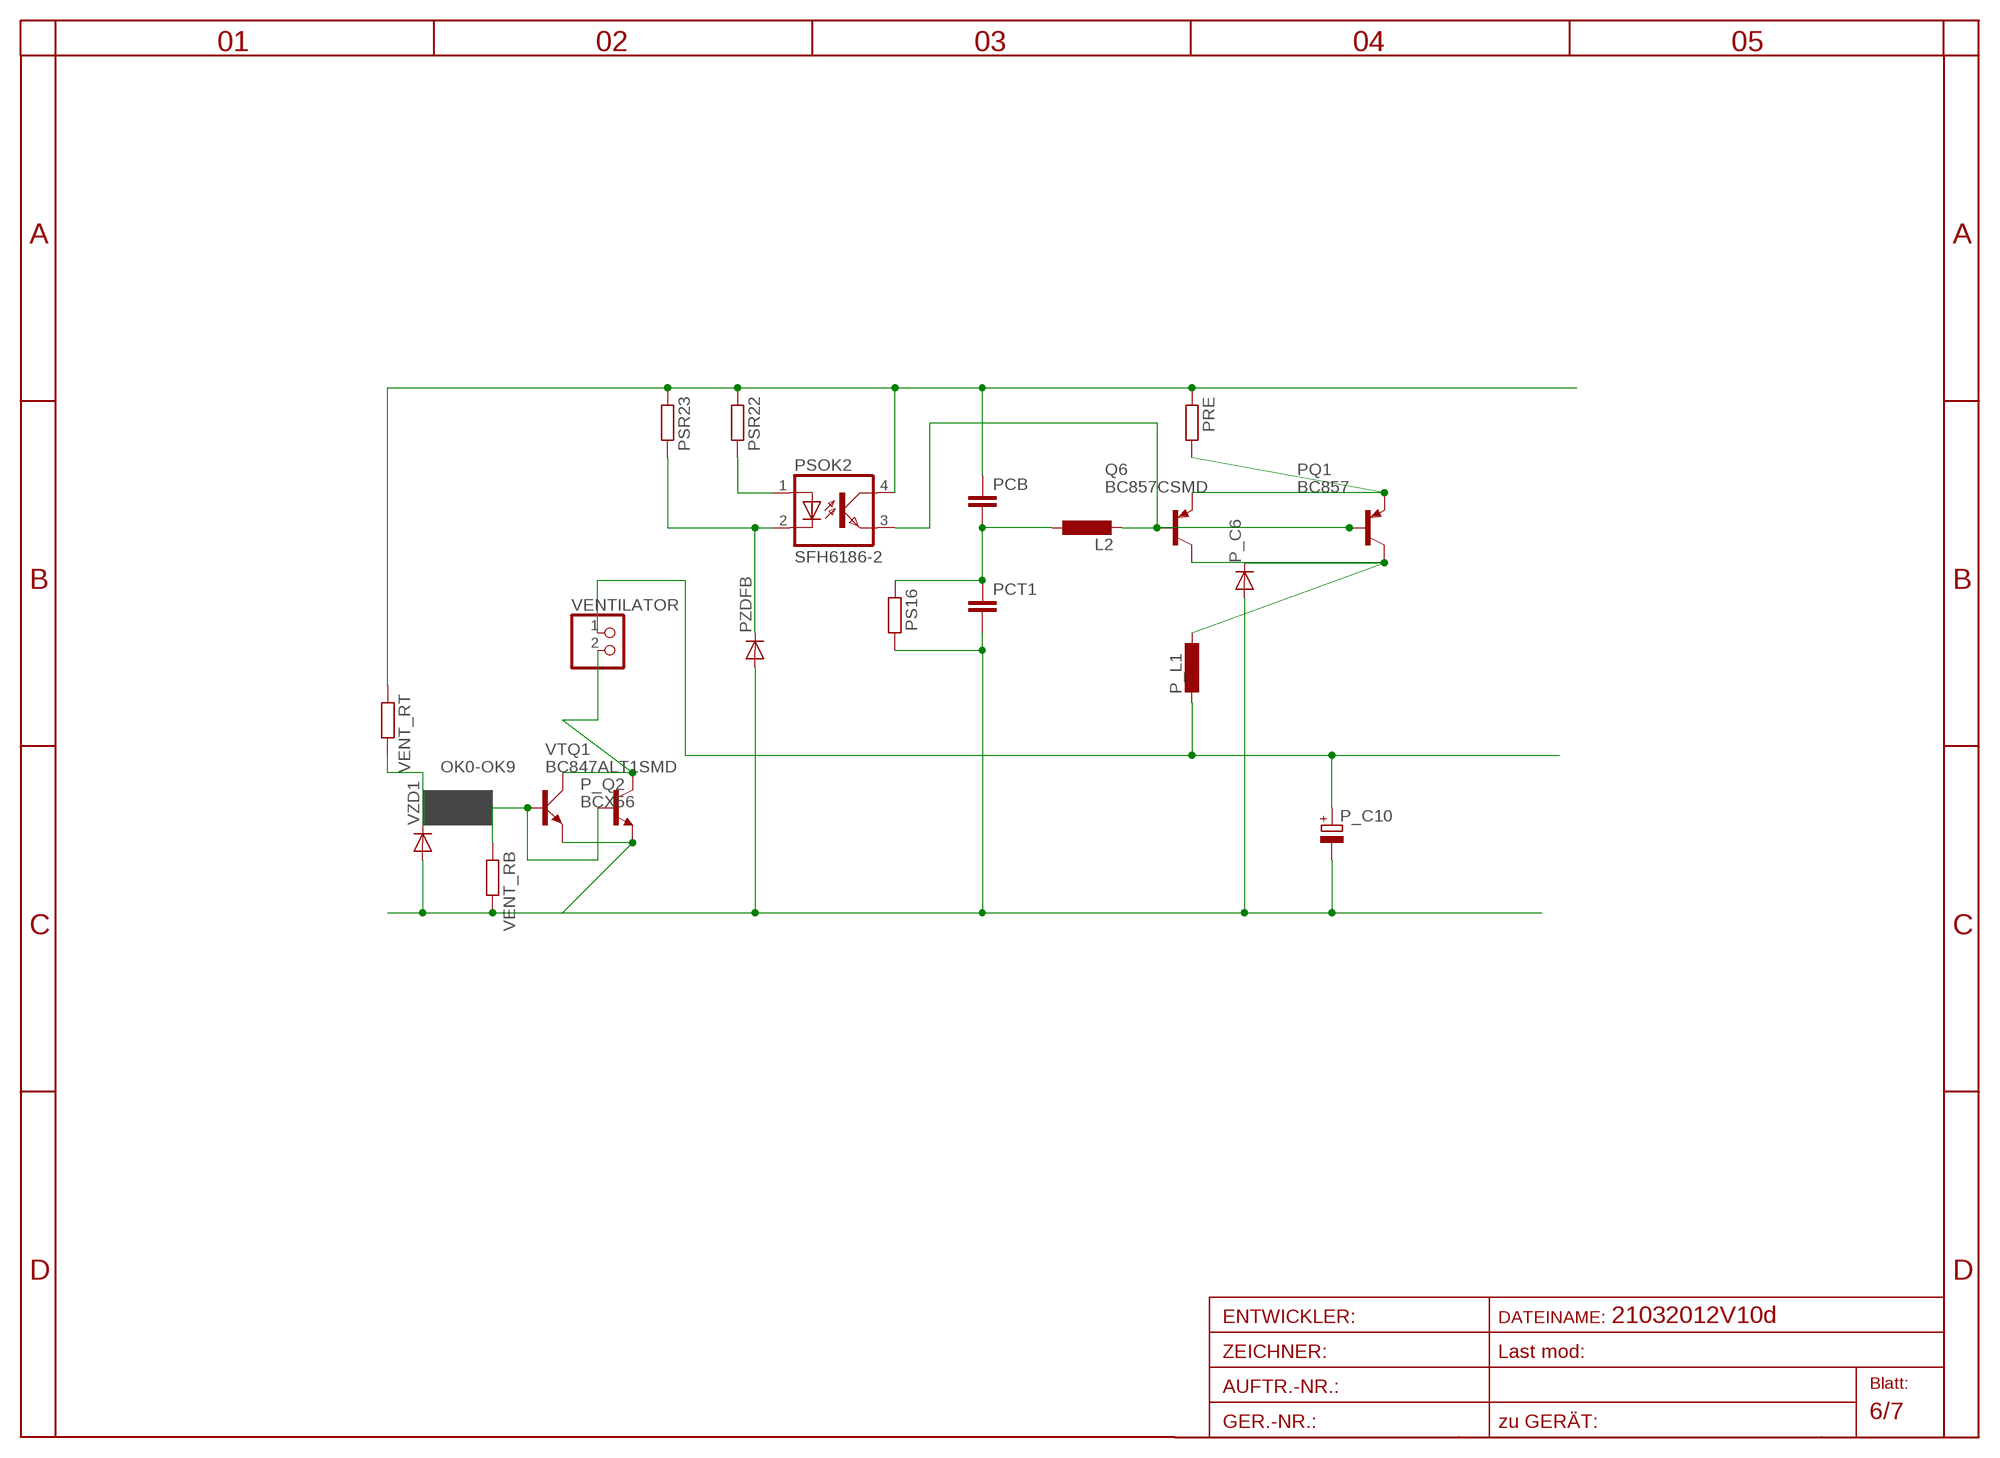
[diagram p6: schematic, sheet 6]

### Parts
L2  L-EUL5650M  [L5650M]
P_C6  DIODE-SMB  [SMB]
P_C10  CPOL-EUE2.5-6  [E2,5-6]
P_L1  L-EUL5650M  [L5650M]
P_Q2  BCX56  [SOT223]
PCB  C-EUC1206  [C1206]
PCT1  C-EUC1206  [C1206]
PQ1  BC857  [SOT223]
PRE  R-EU_R1210  [R1210]
PS16  R-EU_R1206  [R1206]
PSOK2  SFH6186-2  [SMD4]
PSR22  R-EU_R1206  [R1206]
PSR23  R-EU_R1206  [R1206]
PZDFB  DIODE-MINIMELF  [MINIMELF]
Q6  BC857CSMD  [SOT23-BEC]
VENT_RB  R-EU_R1206  [R1206]
VENT_RT  R-EU_R1206  [R1206]
VENTILATOR  PINHD-1X2  [1X02]
VTQ1  BC847ALT1SMD  [SOT23]
VZD1  DIODE-MINIMELF  [MINIMELF]

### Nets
BATT-: P_C6.A P_C10.- P_Q2.3(E) PCT1.2 PS16.2 PZDFB.A VENT_RB.2 VTQ1.2(E) VZD1.A ; also sheet 1,4,5,7
HOT: P_C6.C P_L1.1 PQ1.2(C) Q6.C
N$22: P_C10.+ P_L1.2 VENTILATOR.1 ; also sheet 7
N$38: PQ1.3(E) PRE.2 Q6.E
N$39: L2.2 PQ1.1(B) PSOK2.3(EMIT) Q6.B
N$41: PSOK2.2(C) PSR23.2 PZDFB.C
N$42: PSOK2.1(A) PSR22.2
N$43: L2.1 PCB.2 PCT1.1 PS16.1
N$53: P_Q2.2(C) VENTILATOR.2 VTQ1.3(C)
PLUS11: PCB.1 PRE.1 PSOK2.4(COL) PSR22.1 PSR23.1 VENT_RT.1 ; also sheet 1,4,5,7
VENTB: P_Q2.1(B) VENT_RB.1 VTQ1.1(B) ; also sheet 4
VENTMID: VENT_RT.2 VZD1.C ; also sheet 4

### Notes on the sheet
- OK0-OK9

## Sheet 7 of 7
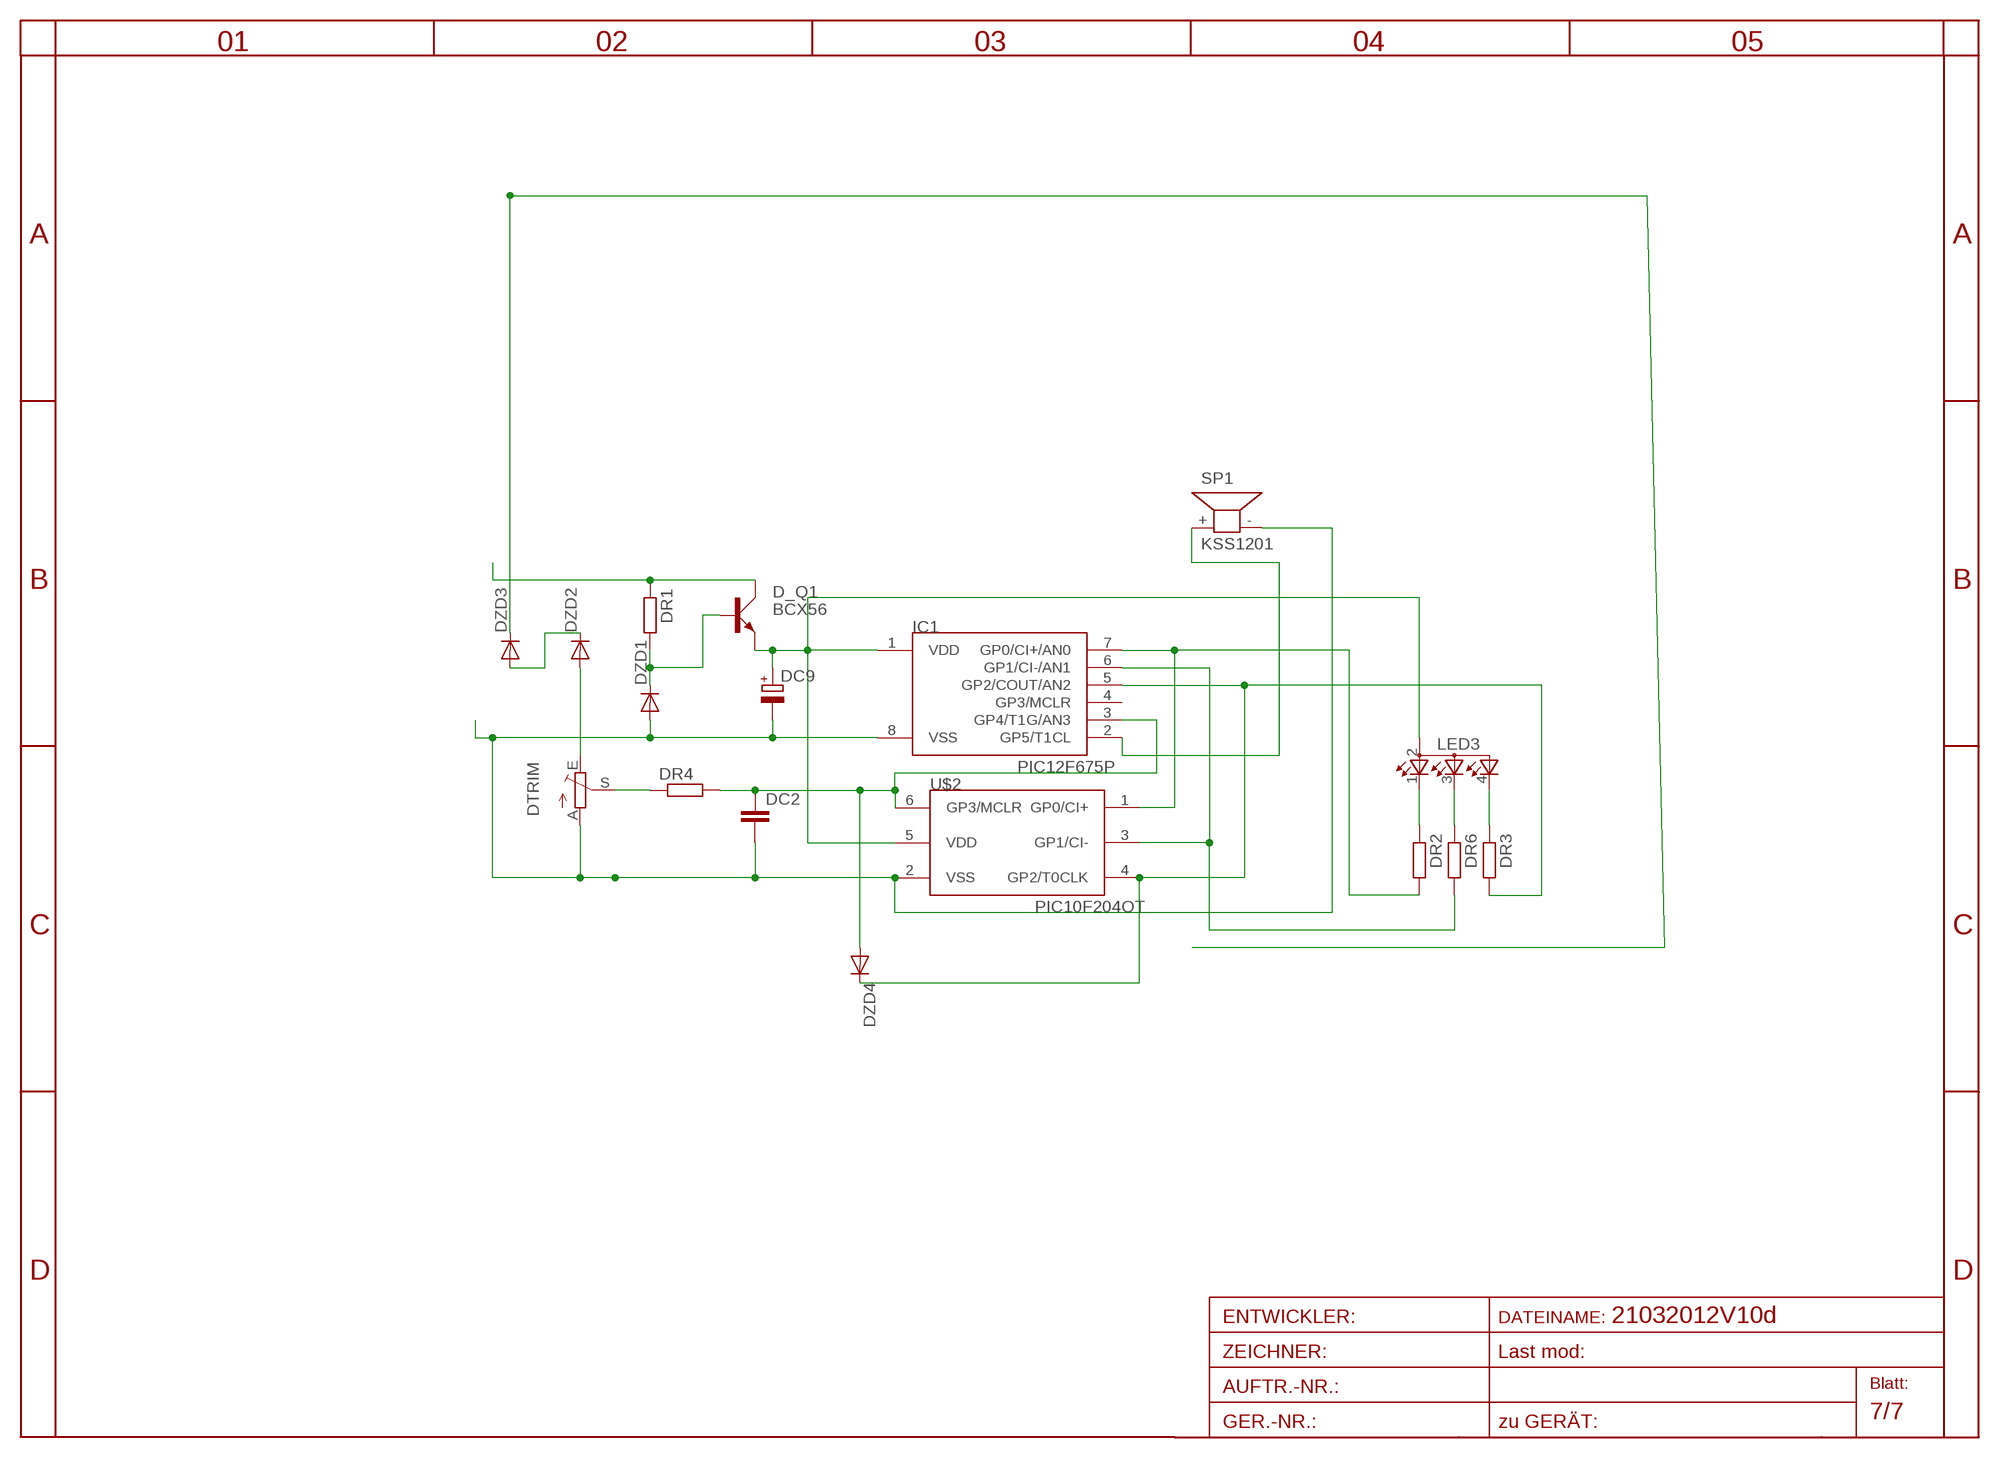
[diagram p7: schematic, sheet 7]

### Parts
D_Q1  BCX56  [SOT223]
DC2  C-EUC1206  [C1206]
DC9  CPOL-EUE5-6  [E5-6]
DR1  R-EU_R1206  [R1206]
DR2  R-EU_R1206  [R1206]
DR3  R-EU_R1206  [R1206]
DR4  R-EU_R1206  [R1206]
DR6  R-EU_R1206  [R1206]
DTRIM  TRIM_EU-EVND_H  [EVND8AA]
DZD1  DIODE-MINIMELF  [MINIMELF]
DZD2  DIODE-MINIMELF  [MINIMELF]
DZD3  DIODE-MINIMELF  [MINIMELF]
DZD4  DIODE-MINIMELF  [MINIMELF]
IC1  PIC12F675P  [DIL8]
LED3  TOPLED-3  [P-LCC-4-3]
SP1  KSS1201  [KSS1201]
U$2  PIC10F204OT  [SOT23-6]

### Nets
BATT-: DC2.2 DC9.- DTRIM.A DZD1.A IC1.8(VSS) SP1.- U$2.2(VSS) ; also sheet 1,4,5,6
N$22: D_Q1.2(C) DR1.1 ; also sheet 6
N$34: D_Q1.3(E) DC9.+ IC1.1(VDD) LED3.2(A2) U$2.5(VDD)
N$35: DR2.2 IC1.7(GP0/CI+/AN0) U$2.1(GP0/CI+)
N$36: DR6.2 IC1.6(GP1/CI-/AN1) U$2.3(GP1/CI-)
N$37: DR3.2 DZD4.C IC1.5(GP2/COUT/AN2) U$2.4(GP2/T0CLK)
N$46: D_Q1.1(B) DR1.2 DZD1.C
N$47: DR2.1 LED3.1(CRED)
N$48: DR6.1 LED3.3(CBLUE)
N$49: DR3.1 LED3.4(CGREEN)
N$69: DTRIM.E DZD2.A
N$75: DC2.1 DR4.2 DZD4.A IC1.3(GP4/T1G/AN3) U$2.6(GP3/MCLR)
N$76: DR4.1 DTRIM.S
N$83: DZD2.C DZD3.A
N$96: IC1.2(GP5/T1CL) SP1.+
PLUS11: DZD3.C ; also sheet 1,4,5,6
Unconnected: IC1.4(GP3/MCLR)

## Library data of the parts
(BATT+) (BATT-) C_VIN+ MINUS1- MINUS2- MINUS3- MINUS4- MINUS5- MINUS6- MINUS7- MINUS8- MINUS9- MINUS10 MINUS60 MINUS120 PLUS1+ PLUS2+ PLUS3+ PLUS4+ PLUS5+ PLUS6+ PLUS7+ PLUS8+ PLUS9+ PLUS10+ PLUS120 VIN(+) VMINUS(-) VOUT(+) VOUT(+)1 VOUT(+)REG VOUT- = pinhead:PINHD-1X1: PIN HEADER
A C CD1 CD31 CD49 D8 D9 D9A D10 D10A D10A1 D12-D15 D17-D30 D33-D40 D43-D46 DZD1-DZD4 P_C6 PZDFB SD1-SD4 VD2 VD-S1 VD-S2 VIO VZDHV = diode:DIODE-: DIODE
A..C LED4-LED7 LED8X LED9 LED9X LED10 LED10X SLED1 = led:LED: LED
C-1083 V-1083 = linear-technology-2:LT1083*: 7.5A Low Dropout Positive Adjustable Regulators
C-MABDT C-MABDT1 = v-reg:LM317?*: 500 mA Adjustable Output Positive Voltage Regulator Source: http://www.onsemi.co.jp .. LM317M-D.PDF
C-SO8 C-TO92 TO92S V-SO8 = v-reg-3:LM317L: Adjustable Voltage Regulator, 1.2V to 37V, 100mA
C-TS V-TS = v-reg:LM317TS: VOLTAGE REGULATOR
C. C.1 = diode-1:1N4148: DIODE
C_HV_Q C_REG_Q = transistor-power:BD139: NPN TRANSISTOR
C_OPTN1 CR1-CR5 DR1-DR4 DR6 FR1-FR6 PRE PS16 PSR22 PSR23 R6 SR1-SR6 VENT_RB VENT_RT VO1 VO2 VR2X VR3 VR3X VR8X VR11-VR15 VR20 VR21 VR24-VR39 VR41 VR42 VR44 VR46-VR73 VRB1 VRB2 VRHV VRT1-VRT3 = rcl-2:R-EU_: RESISTOR, European symbol
CC1 CC3 DC2 PCB PCT1 VC4 VCHI VCLO = rcl:C-EU: CAPACITOR, European symbol
CC4 DC9 P_C10 VCAD VCIN VCOUT = rcl:CPOL-EU: POLARIZED CAPACITOR, European symbol
CD4 = diode:BAS40-04: Silicon Schottky Diodes General-purpose diode for high-speed switching
CTRIM2 CTRIM3 DTRIM R22 STRIM01 TRIM1-9 TRIM2-7 TRIM2-9 TRIM3-9 TRIM5X TRIM7X TRIM8X TRIM9X TRIM10X VPOT1 VPOT2 VTRIM1 = pot:TRIM_EU-: POTENTIOMETER
D_Q1 P_Q2 = transistor-power:BCX56
F2 VFUSE = fuse:SHK20Q: FUSE HOLDER 5 x 20 mm, SH contact, E1207 Buerklin 64G6061
FC1 = rcl-2:C-EU: CAPACITOR, European symbol
FD1 = diode-1:ZENER-DIODE: Z-Diode
FQ1 = transistor-pnp:BC807*: PNP Transistror
FQ2 = transistor:BC846: NPN TRANSISTOR
IC1 = microchip-5:PIC12F6*: uPC nW 1k Program Flash memory 2x Timer Comparator 10b A/D converter/ 4xIN
L2 P_L1 = rcl:L-EU: INDUCTOR, European symbol
LED3 = led:TOPLED-3: OSRAM - Hyper Multi TOPLED® (RGB) LB E673, LV E673, LT E673 - Power TOPLED® Enhanced optical Power LED (HOP2000) LS E67B, LA E67B, LO E67B, LY E67B - Hyper Multi TOPLED® Enhanced optical Power LED (HOP2000 / ATON®) LATB T66B - Hyper Multi TOPLED® Hyper-Bright LED LATB T686 Source: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
OK1 OK2X OK3 OK4X OK5X OK6X OK7 OK8X OK9X OK10X PSOK2 = optocoupler:SFH618?*: Optocoupler, Phototransistor Output, Low Input Current Source: http://www.vishay.com/docs/83673/sfh618.pdf
OUT+ VIN(-) VIN(-)1 VIN+1 = pinhead(2):PINHD-1X1: PIN HEADER
PQ1 Q6 Q14 Q19 Q30-Q36 SQ1 = transistor-pnp:BC857*: PNP Transistror
Q1 Q21 Q29 Q38-Q44 = transistor-power:TIP142: NPN DARLINGTON TRANSISTOR
Q1T Q2S Q2T Q3 Q7-Q9 Q10S Q15-Q18 Q20 Q22-Q28 = transistor-power:TIP120: NPN DARLINGTON TRANSISTOR
Q5 = transistor-fet:FDD4141: P-Channel PowerTrench® MOSFET Source: FDD4141.pdf
R2-R5 R13 R14 R16 R18 R21 R24 VR-B = rcl:R-EU_: RESISTOR, European symbol
S1 = switch:320-938: TOGGLE SWITCH distributor RS Components
SP1 = buzzer:KSS1201: SPEAKER
U$2 = microchip-5:PIC10F2*: uPC nW 0,25/0,5k Program Flash memory Comparator
V-TO1 V-TO3 = v-reg:LM317-TO3: VOLTAGE REGULATOR
VCQ = transistor-npn:BC817*: NPN Transistor
VENTILATOR = pinhead(2):PINHD-1X2: PIN HEADER
VQHV = transistor-power:TIP41C: NPN TRANSISTOR
VTQ1 = transistor-npn:BC847*: NPN Transistor
VZD1 = diode-1:DIODE-: DIODE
